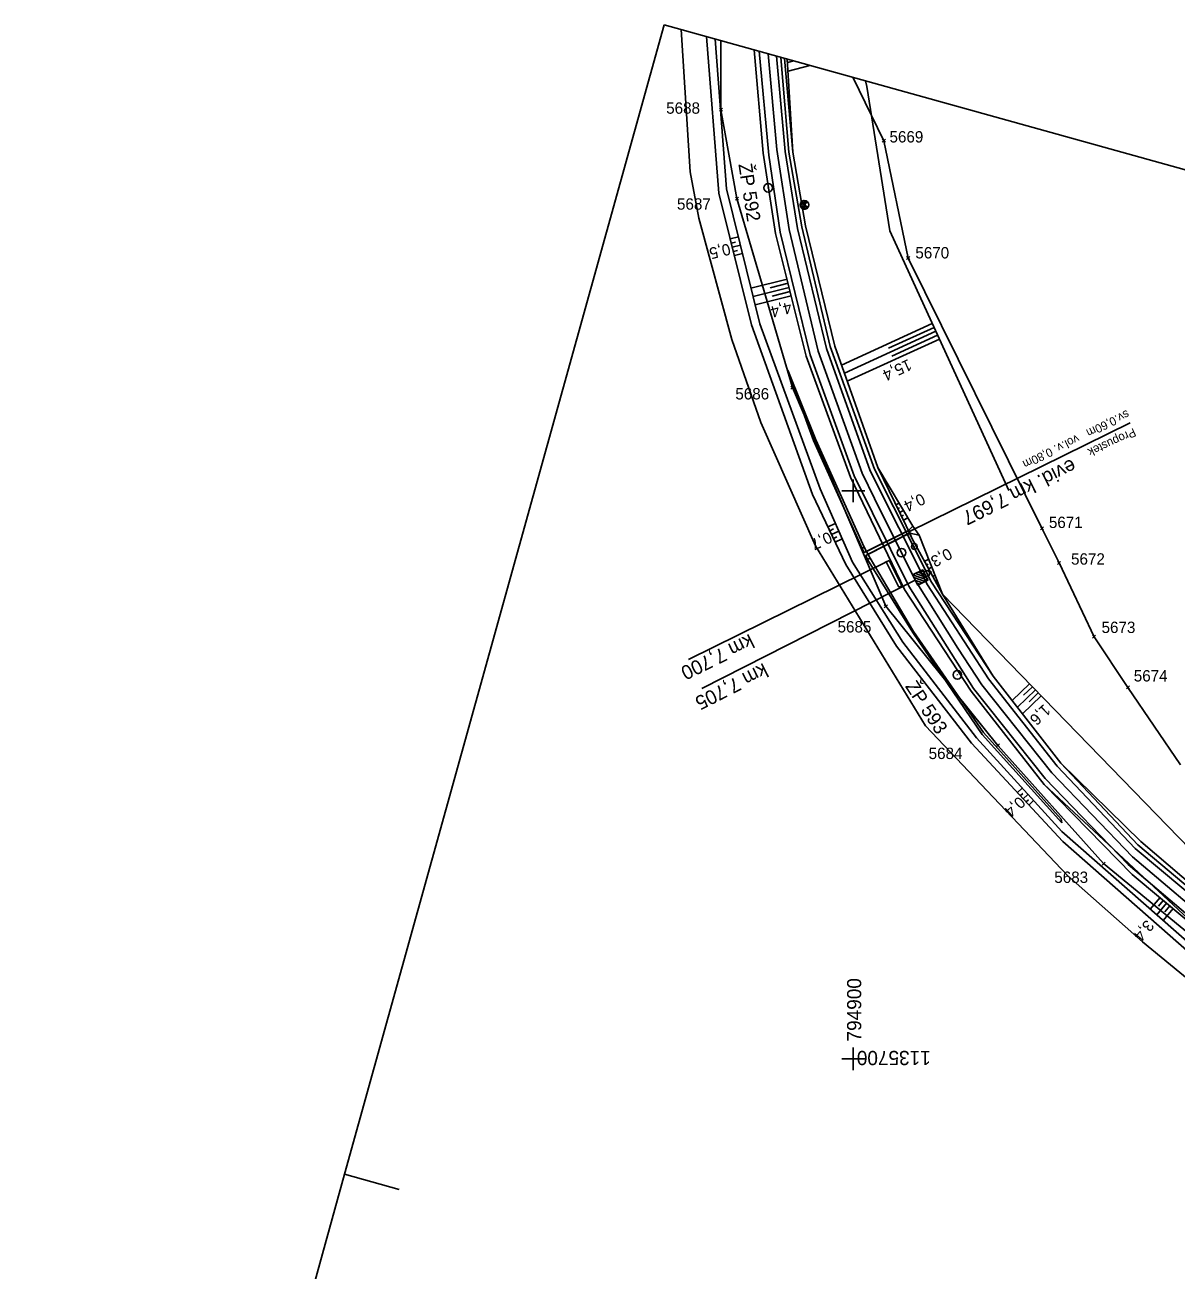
# Model space of a CAD drawing. Extents: x -795046 to -794647, y -1136002 to -1135518.
# Drawn here: x -795045.8 to -794843.2, y -1135737.2 to -1135518 of the extents above; entities that cross this region are included whole.
import ezdxf

# ---------------------------------------------------------------- set-up
doc = ezdxf.new("R2010")
doc.units = 0
for name, color, linetype in [('0381KM005-009P - Vrstva 1', 7, 'Continuous'), ('0381KM005-009P - Vrstva 13', 7, 'Continuous'), ('0381KM005-009P - Vrstva 19', 7, 'Continuous'), ('0381KM005-009P - Vrstva 28', 7, 'Continuous'), ('0381KM005-009P - Vrstva 3', 7, 'Continuous'), ('0381KM005-009P - Vrstva 4', 7, 'Continuous'), ('0381KM005-009P - Vrstva 48', 7, 'Continuous'), ('0381KM005-009P - Vrstva 49', 7, 'Continuous'), ('0381KM005-009P - Vrstva 51', 7, 'Continuous'), ('0381KM005-009P - Vrstva 55', 7, 'Continuous'), ('0381KM005-009P - Vrstva 7', 7, 'Continuous'), ('0381KM005-009P - Vrstva 9', 7, 'Continuous'), ('formát', 7, 'Continuous'), ('krizky_1000 - souradnice', 7, 'Continuous'), ('krizky_1000 - Vrstva 1', 7, 'Continuous'), ('szdc - hran DP', 7, 'Continuous'), ('szdc - szdc_cislo', 7, 'Continuous'), ('szdc - szdc_krizek', 7, 'Continuous'), ('vyt_sit - stávající', 7, 'Continuous')]:
    doc.layers.add(name, color=color, linetype=linetype)

msp = doc.modelspace()

# ---------------------------------------------------------------- linework, layer by layer
at = {"layer": '0381KM005-009P - Vrstva 1'}
msp.add_lwpolyline([(-794915, -1135523.08), (-794913.46, -1135539.92), (-794911.29, -1135554.01), (-794906.18, -1135575.42), (-794898.43, -1135596.89), (-794896.25, -1135601.39), (-794889.11, -1135615.73), (-794881.58, -1135627.73), (-794877.36, -1135634.16), (-794865.05, -1135649.67), (-794850.87, -1135664.43), (-794835.06, -1135677.82), (-794817.77, -1135689.58), (-794801.57, -1135698.91), (-794785.04, -1135707.72), (-794765.11, -1135718.4), (-794746.17, -1135729.82), (-794729.27, -1135742.41), (-794716.02, -1135754.58), (-794701.99, -1135770.6), (-794697.2, -1135777.62)], dxfattribs=at)
at = {"layer": '0381KM005-009P - Vrstva 13'}
for points in [[(-794898.09, -1135609.93), (-794898.09, -1135609.93), (-794906.6, -1135591.05), (-794911.52, -1135578.79), (-794907, -1135591.18), (-794898.46, -1135610.15), (-794898.09, -1135609.93)], [(-794897.05, -1135611.89), (-794897.51, -1135612.1), (-794889.51, -1135624.97), (-794877.31, -1135642.92), (-794863.33, -1135658.49)], [(-794863.33, -1135658.49), (-794863.44, -1135657.81), (-794877.06, -1135642.57), (-794889.39, -1135624.78), (-794897.05, -1135611.89)]]:
    msp.add_lwpolyline(points, dxfattribs=at)
at = {"layer": '0381KM005-009P - Vrstva 19'}
for p, q in [((-794890.22, -1135607.23), (-794851.25, -1135588.05)), ((-794898.08, -1135610.9), (-794890.26, -1135606.98)), ((-794890.03, -1135607.47), (-794897.8, -1135611.38)), ((-794890.24, -1135606.98), (-794897.66, -1135610.68)), ((-794897.41, -1135611.19), (-794890.06, -1135607.43))]:
    msp.add_line(p, q, dxfattribs=at)
for points in [[(-794890.7, -1135606.17), (-794890.26, -1135606.98), (-794890.24, -1135606.98), (-794890.06, -1135607.43), (-794890.03, -1135607.47), (-794889.7, -1135608.37)], [(-794898.09, -1135609.93), (-794897.05, -1135611.89), (-794897.51, -1135612.1), (-794897.8, -1135611.38), (-794897.41, -1135611.19), (-794897.66, -1135610.68), (-794898.08, -1135610.9), (-794898.46, -1135610.15)]]:
    msp.add_lwpolyline(points, close=True, dxfattribs=at)
at = {"layer": '0381KM005-009P - Vrstva 28'}
msp.add_line((-794887.06, -1135614.6), (-794887.11, -1135614.51), dxfattribs=at)
msp.add_circle((-794887.08, -1135614.55), 0.5, dxfattribs=at)
at = {"layer": '0381KM005-009P - Vrstva 3'}
for p, q in [((-794889.11, -1135615.73), (-794926.66, -1135634.8)), ((-794886.88, -1135615.74), (-794889.56, -1135614.84)), ((-794887.35, -1135615.97), (-794889.32, -1135615.31)), ((-794887.11, -1135615.26), (-794889.08, -1135614.6)), ((-794887.83, -1135616.21), (-794889.08, -1135615.79)), ((-794888.3, -1135616.45), (-794888.85, -1135616.26)), ((-794887.35, -1135614.79), (-794888.61, -1135614.36)), ((-794887.58, -1135614.31), (-794888.13, -1135614.13))]:
    msp.add_line(p, q, dxfattribs=at)
msp.add_lwpolyline([(-794888.67, -1135616.63), (-794889.56, -1135614.84), (-794887.76, -1135613.95), (-794886.88, -1135615.74)], close=True, dxfattribs=at)
at = {"layer": '0381KM005-009P - Vrstva 4'}
for points in [[(-794917.47, -1135522.4), (-794915.85, -1135540.59), (-794913.67, -1135554.7), (-794908.27, -1135576.33), (-794900.49, -1135597.63), (-794890.98, -1135617.37), (-794879.27, -1135635.32), (-794866.44, -1135651.71), (-794836.69, -1135679.46), (-794818.84, -1135691.63), (-794786.57, -1135709.39), (-794766.3, -1135721.02), (-794748.58, -1135730.93), (-794731.42, -1135743.47), (-794717.51, -1135756.55), (-794703.68, -1135772.07), (-794698, -1135780.52)], [(-794697.72, -1135779.5), (-794703.02, -1135771.54), (-794717.11, -1135755.66), (-794731.12, -1135742.73), (-794748.15, -1135730.35), (-794763.88, -1135720.89), (-794786.11, -1135708.79), (-794818.08, -1135691.13), (-794836.08, -1135678.99), (-794851.61, -1135665.79), (-794866.22, -1135650.67), (-794878.82, -1135634.83), (-794890.24, -1135616.8), (-794899.85, -1135597.37), (-794907.59, -1135576.09), (-794912.87, -1135554.46), (-794914.85, -1135540.94), (-794916.58, -1135522.65)], [(-794696.7, -1135775.84), (-794700.88, -1135769.71), (-794714.51, -1135754.08), (-794728.76, -1135740.91), (-794743.23, -1135730.04), (-794762.73, -1135718.04), (-794783.1, -1135707.11), (-794816.84, -1135688.49), (-794833.24, -1135677.32), (-794850.38, -1135662.96), (-794864.1, -1135648.49), (-794876.22, -1135633.13), (-794886.94, -1135616.58), (-794897.05, -1135596.51), (-794904.69, -1135574.95), (-794909.82, -1135553.82), (-794912.02, -1135540.3), (-794913.51, -1135523.5)], [(-794912.74, -1135523.71), (-794911.32, -1135540.41), (-794909.07, -1135553.52), (-794904.05, -1135574.62), (-794896.27, -1135596.21), (-794886.26, -1135616.08), (-794875.38, -1135632.64), (-794863.5, -1135647.94), (-794849.93, -1135662.35), (-794832.65, -1135676.88), (-794816.85, -1135687.92), (-794782.78, -1135706.49), (-794762.23, -1135717.77), (-794742.47, -1135729.7), (-794727.73, -1135739.54), (-794713.83, -1135753.13), (-794700.2, -1135769.22), (-794696.4, -1135774.74)]]:
    msp.add_lwpolyline(points, dxfattribs=at)
at = {"layer": '0381KM005-009P - Vrstva 48'}
for p, q in [((-794910.48, -1135524.34), (-794911.58, -1135524.64)), ((-794907.65, -1135525.13), (-794911.49, -1135526.17)), ((-794921.65, -1135555.69), (-794920.21, -1135555.33)), ((-794921.47, -1135556.42), (-794920.75, -1135556.24)), ((-794921.29, -1135557.15), (-794919.85, -1135556.79)), ((-794921.11, -1135557.88), (-794920.39, -1135557.7)), ((-794920.93, -1135558.6), (-794919.5, -1135558.25)), ((-794911.66, -1135562.77), (-794918.01, -1135564.35)), ((-794911.47, -1135563.49), (-794914.65, -1135564.29)), ((-794911.29, -1135564.22), (-794917.65, -1135565.81)), ((-794910.93, -1135565.68), (-794917.29, -1135567.27)), ((-794911.11, -1135564.95), (-794914.29, -1135565.74)), ((-794886.1, -1135570.57), (-794902.06, -1135577.88)), ((-794885.48, -1135571.93), (-794901.56, -1135579.3)), ((-794885.79, -1135571.25), (-794893.8, -1135574.92)), ((-794884.85, -1135573.3), (-794901.06, -1135580.72)), ((-794885.17, -1135572.61), (-794893.24, -1135576.31)), ((-794892.51, -1135602.47), (-794891.95, -1135602.19)), ((-794892.18, -1135603.14), (-794891.87, -1135602.99)), ((-794891.85, -1135603.81), (-794891.18, -1135603.49)), ((-794891.52, -1135604.49), (-794891.16, -1135604.31)), ((-794891.19, -1135605.16), (-794890.41, -1135604.78)), ((-794904.48, -1135606.38), (-794903.16, -1135605.75)), ((-794904.16, -1135607.05), (-794903.51, -1135606.74)), ((-794903.83, -1135607.73), (-794902.56, -1135607.12)), ((-794903.51, -1135608.41), (-794902.89, -1135608.11)), ((-794903.19, -1135609.08), (-794901.96, -1135608.5)), ((-794887.47, -1135612.45), (-794886.76, -1135612.05)), ((-794887.11, -1135613.1), (-794886.8, -1135612.93)), ((-794886.75, -1135613.76), (-794886.2, -1135613.46)), ((-794886.39, -1135614.42), (-794886.16, -1135614.29)), ((-794886.03, -1135615.08), (-794885.64, -1135614.87)), ((-794869.01, -1135633.98), (-794872.05, -1135636.93)), ((-794867.96, -1135635.05), (-794871.12, -1135638.12)), ((-794868.48, -1135634.52), (-794870.03, -1135636.02)), ((-794867.44, -1135635.59), (-794869.05, -1135637.16)), ((-794866.92, -1135636.13), (-794870.2, -1135639.31)), ((-794871.13, -1135653.14), (-794870.27, -1135652.34)), ((-794870.62, -1135653.69), (-794870.19, -1135653.29)), ((-794870.11, -1135654.24), (-794869.27, -1135653.46)), ((-794869.6, -1135654.79), (-794869.18, -1135654.4)), ((-794869.09, -1135655.34), (-794868.26, -1135654.56)), ((-794846.02, -1135671.64), (-794847.73, -1135673.69)), ((-794844.87, -1135672.6), (-794846.61, -1135674.68)), ((-794845.45, -1135672.12), (-794846.31, -1135673.15)), ((-794844.3, -1135673.09), (-794845.17, -1135674.13)), ((-794843.72, -1135673.57), (-794845.48, -1135675.67))]:
    msp.add_line(p, q, dxfattribs=at)
at = {"layer": '0381KM005-009P - Vrstva 49'}
for p, q in [((-794912.11, -1135523.89), (-794910.64, -1135540.4)), ((-794890.7, -1135606.17), (-794890.26, -1135606.98)), ((-794890.26, -1135606.98), (-794889.55, -1135606.22)), ((-794890.03, -1135607.47), (-794888.43, -1135607.82)), ((-794889.7, -1135608.37), (-794890.03, -1135607.47))]:
    msp.add_line(p, q, dxfattribs=at)
for points in [[(-794925.83, -1135520.07), (-794923.66, -1135547.6), (-794917.9, -1135570.81), (-794907.19, -1135600.69), (-794901.33, -1135612.99), (-794892.4, -1135627.36), (-794879.19, -1135644.46), (-794863.1, -1135661.78), (-794838.91, -1135683.03), (-794815.97, -1135701.12), (-794794.79, -1135715.61), (-794782.46, -1135721.1), (-794767.75, -1135725.5), (-794750.75, -1135732.17), (-794732.98, -1135744.75), (-794719.14, -1135757.73), (-794705.45, -1135773.64), (-794699.07, -1135784.37)], [(-794749.75, -1135730.99), (-794767.46, -1135724.56), (-794782.23, -1135720.17), (-794794.11, -1135714.55), (-794814.96, -1135700.02), (-794837.43, -1135682.73), (-794863.32, -1135660), (-794878.31, -1135643.5), (-794891.31, -1135626.67), (-794900.17, -1135612.61), (-794905.81, -1135599.68), (-794916.46, -1135570.65), (-794922.29, -1135546.83), (-794924.31, -1135520.49)], [(-794917.47, -1135522.4), (-794915.85, -1135540.59), (-794913.67, -1135554.7), (-794908.27, -1135576.33), (-794900.49, -1135597.63), (-794890.98, -1135617.37), (-794879.27, -1135635.32), (-794866.44, -1135651.71), (-794850.9, -1135667.56)], [(-794911.62, -1135524.02), (-794910.64, -1135540.4), (-794908.42, -1135553.38), (-794903.23, -1135574.56), (-794895.71, -1135595.89), (-794889.55, -1135606.22), (-794888.43, -1135607.82), (-794884.32, -1135618.22)], [(-794897.87, -1135527.85), (-794897.6, -1135528.83), (-794893.57, -1135554.26), (-794872.65, -1135599.94)], [(-794895.71, -1135595.89), (-794890.7, -1135606.17)], [(-794889.7, -1135608.37), (-794884.32, -1135618.22), (-794824.85, -1135679.44), (-794811.36, -1135687.77), (-794786.09, -1135699.38), (-794707.09, -1135741.45)], [(-794863.5, -1135647.94), (-794875.38, -1135632.64), (-794884.32, -1135618.22)], [(-794695.93, -1135773.08), (-794698.78, -1135768.51), (-794712.94, -1135751.52), (-794727.73, -1135739.54), (-794743.72, -1135728.23), (-794763.92, -1135716.02), (-794781.48, -1135706.54), (-794800.89, -1135696.32), (-794816.57, -1135687.28), (-794832.17, -1135676.47), (-794849.4, -1135661.77), (-794863.5, -1135647.94)], [(-794850.9, -1135667.56), (-794836.69, -1135679.46), (-794818.84, -1135691.63), (-794803.16, -1135702.98), (-794784.32, -1135712.45), (-794768.51, -1135721.35), (-794758.17, -1135725.72), (-794749.71, -1135730.94)]]:
    msp.add_lwpolyline(points, dxfattribs=at)
at = {"layer": '0381KM005-009P - Vrstva 51'}
msp.add_lwpolyline([(-794699.07, -1135784.37), (-794705.45, -1135773.64), (-794719.14, -1135757.73), (-794732.98, -1135744.75), (-794750.75, -1135732.17), (-794767.75, -1135725.5), (-794782.46, -1135721.1), (-794794.79, -1135715.61), (-794815.97, -1135701.12), (-794838.91, -1135683.03), (-794863.1, -1135661.78), (-794879.19, -1135644.46), (-794892.4, -1135627.36), (-794901.33, -1135612.99), (-794907.19, -1135600.69), (-794917.9, -1135570.81), (-794923.66, -1135547.6), (-794925.83, -1135520.07)], dxfattribs=at)
at = {"layer": '0381KM005-009P - Vrstva 55'}
msp.add_lwpolyline([(-794930.32, -1135518.82), (-794928.69, -1135543.86), (-794927.18, -1135552.03), (-794921.37, -1135573.41), (-794916.26, -1135587.98), (-794906.67, -1135609.69), (-794887.27, -1135641.42), (-794862.33, -1135667.74), (-794849.1, -1135679.42), (-794837.63, -1135688.88), (-794826.42, -1135697.51), (-794808.25, -1135711.35), (-794792.02, -1135721.49), (-794781.13, -1135725.75), (-794765.57, -1135730.81), (-794749.96, -1135737.95), (-794742.14, -1135743.85), (-794737.72, -1135738.96), (-794727.83, -1135728.01), (-794718.43, -1135717.37), (-794692.54, -1135688.86), (-794715.68, -1135650.06)], dxfattribs=at)
at = {"layer": '0381KM005-009P - Vrstva 7'}
msp.add_line((-794889.24, -1135609.86), (-794889.28, -1135609.77), dxfattribs=at)
for centre, radius in [((-794889.26, -1135609.81), 0.5), ((-794891.51, -1135610.91), 0.75)]:
    msp.add_circle(centre, radius, dxfattribs=at)
at = {"layer": '0381KM005-009P - Vrstva 9'}
for p, q in [((-794893.93, -1135612.39), (-794929, -1135629.69)), ((-794894.19, -1135612.52), (-794894.73, -1135612.79)), ((-794893.66, -1135612.26), (-794894.19, -1135612.52)), ((-794894.19, -1135612.52), (-794892, -1135617.01)), ((-794891.46, -1135616.75), (-794893.66, -1135612.26)), ((-794892, -1135617.01), (-794891.46, -1135616.75))]:
    msp.add_line(p, q, dxfattribs=at)
at = {"layer": 'formát'}
for p, q in [((-794933.28, -1135518), (-794989.53, -1135720.33)), ((-794933.28, -1135518), (-794647.13, -1135597.56)), ((-794989.53, -1135720.33), (-795045.79, -1135922.65)), ((-794989.53, -1135720.33), (-794979.9, -1135723.01))]:
    msp.add_line(p, q, dxfattribs=at)
at = {"layer": 'krizky_1000 - Vrstva 1'}
for points in [[(-794900, -1135598), (-794900, -1135602)], [(-794902, -1135600), (-794898, -1135600)], [(-794900, -1135698), (-794900, -1135702)], [(-794902, -1135700), (-794898, -1135700)]]:
    msp.add_lwpolyline(points, dxfattribs=at)
at = {"layer": 'szdc - hran DP'}
for p, q in [((-794923.29, -1135532.94), (-794923.3, -1135520.77)), ((-794900.1, -1135527.22), (-794894.63, -1135538.4)), ((-794920.48, -1135548.58), (-794923.29, -1135532.94)), ((-794894.63, -1135538.4), (-794890.34, -1135559.06)), ((-794910.72, -1135581.84), (-794920.48, -1135548.58)), ((-794890.34, -1135559.06), (-794866.81, -1135606.62)), ((-794894.27, -1135620.34), (-794910.72, -1135581.84)), ((-794866.81, -1135606.62), (-794863.8, -1135612.72)), ((-794863.8, -1135612.72), (-794857.64, -1135625.71)), ((-794874.54, -1135644.85), (-794894.27, -1135620.34)), ((-794857.64, -1135625.71), (-794851.67, -1135634.62)), ((-794851.67, -1135634.62), (-794842.4, -1135648.25)), ((-794855.96, -1135665.64), (-794874.54, -1135644.85)), ((-794807.25, -1135705.8), (-794855.96, -1135665.64))]:
    msp.add_line(p, q, dxfattribs=at)
at = {"layer": 'szdc - szdc_krizek'}
for p, q in [((-794923.03, -1135533.21), (-794923.56, -1135532.68)), ((-794923.56, -1135533.21), (-794923.03, -1135532.68)), ((-794894.36, -1135538.67), (-794894.9, -1135538.14)), ((-794894.9, -1135538.67), (-794894.36, -1135538.14)), ((-794920.21, -1135548.84), (-794920.75, -1135548.31)), ((-794920.75, -1135548.84), (-794920.21, -1135548.31)), ((-794890.08, -1135559.32), (-794890.61, -1135558.79)), ((-794890.61, -1135559.32), (-794890.08, -1135558.79)), ((-794910.46, -1135582.1), (-794910.99, -1135581.57)), ((-794910.99, -1135582.1), (-794910.46, -1135581.57)), ((-794866.55, -1135606.89), (-794867.08, -1135606.35)), ((-794867.08, -1135606.89), (-794866.55, -1135606.35)), ((-794863.54, -1135612.99), (-794864.07, -1135612.46)), ((-794864.07, -1135612.99), (-794863.54, -1135612.46)), ((-794894.01, -1135620.6), (-794894.54, -1135620.07)), ((-794894.54, -1135620.6), (-794894.01, -1135620.07)), ((-794857.38, -1135625.98), (-794857.91, -1135625.45)), ((-794857.91, -1135625.98), (-794857.38, -1135625.45)), ((-794851.41, -1135634.89), (-794851.94, -1135634.35)), ((-794851.94, -1135634.89), (-794851.41, -1135634.35)), ((-794874.28, -1135645.11), (-794874.81, -1135644.58)), ((-794874.81, -1135645.11), (-794874.28, -1135644.58)), ((-794855.7, -1135665.91), (-794856.23, -1135665.38)), ((-794856.23, -1135665.91), (-794855.7, -1135665.38))]:
    msp.add_line(p, q, dxfattribs=at)
at = {"layer": 'vyt_sit - stávající'}
for p, q in [((-794914.98, -1135546.62), (-794914.96, -1135546.72)), ((-794908.58, -1135549.69), (-794909.2, -1135549.24)), ((-794908.46, -1135549.52), (-794909.05, -1135549.09)), ((-794909.02, -1135550.3), (-794908.58, -1135549.69)), ((-794908.4, -1135550.43), (-794908.87, -1135550.09)), ((-794908.28, -1135549.28), (-794908.74, -1135548.94)), ((-794908.1, -1135550.28), (-794908.69, -1135549.85)), ((-794908.13, -1135549.07), (-794908.58, -1135549.69)), ((-794908.58, -1135549.69), (-794907.96, -1135550.14)), ((-794881.72, -1135632.38), (-794881.67, -1135632.47))]:
    msp.add_line(p, q, dxfattribs=at)
for centre, radius in [((-794914.97, -1135546.67), 0.756), ((-794908.58, -1135549.69), 0.764), ((-794881.69, -1135632.43), 0.756)]:
    msp.add_circle(centre, radius, dxfattribs=at)
for radius, start, end in [(0.765, 53.9818, 143.8753), (0.764, 233.293, 323.611)]:
    msp.add_arc((-794908.58, -1135549.69), radius, start, end, dxfattribs=at)

# ---------------------------------------------------------------- texts
at = {"layer": '0381KM005-009P - Vrstva 19'}
for s, height, rotation, p in [('sv.0,60m   vol.v. 0,80m', 1.5, 206.2068, (-794851.86, -1135585.74)), ('Propustek', 1.5, 204.6627, (-794850.69, -1135588.94)), ('evid. km 7,697', 2.5, 206.2068, (-794861.56, -1135594.31))]:
    msp.add_text(s, height=height, rotation=rotation, dxfattribs=at).set_placement(p)
at = {"layer": '0381KM005-009P - Vrstva 3'}
msp.add_text('km 7,705', height=2.5, rotation=206.9201, dxfattribs=at).set_placement((-794915.82, -1135630.27))
at = {"layer": '0381KM005-009P - Vrstva 48'}
for s, rotation, p in [('0,5', 193.9485, (-794921.9, -1135556.44)), ('4,4', 194.0238, (-794911.11, -1135566.74)), ('15,4', 204.6063, (-794890.3, -1135576.77)), ('0,4', 205.994, (-794887.97, -1135600.39)), ('0,7', 205.5118, (-794904.35, -1135607.14)), ('0,3', 208.6712, (-794883.32, -1135610.02)), ('1,6', 224.1646, (-794866.45, -1135637.45)), ('0,4', 222.9053, (-794870.87, -1135653.69)), ('3,4', 230.0673, (-794848.42, -1135675.4))]:
    msp.add_text(s, height=2, rotation=rotation, dxfattribs=at).set_placement(p)
at = {"layer": '0381KM005-009P - Vrstva 9'}
msp.add_text('km 7,700', height=2.5, rotation=206.0861, dxfattribs=at).set_placement((-794918.25, -1135625.14))
at = {"layer": 'krizky_1000 - souradnice'}
for s, rotation, p in [('794900', 90, (-794898.6, -1135696.96)), ('1135700', 180, (-794886.37, -1135698.62))]:
    msp.add_text(s, height=2.5, rotation=rotation, dxfattribs=at).set_placement(p)
at = {"layer": 'szdc - szdc_cislo'}
for s, p in [('5688', (-794932.93, -1135533.64)), ('5669', (-794893.63, -1135538.7)), ('5687', (-794931.03, -1135550.53)), ('5670', (-794889.08, -1135559.11)), ('5686', (-794920.76, -1135583.94)), ('5671', (-794865.58, -1135606.57)), ('5672', (-794861.68, -1135613.02)), ('5685', (-794902.77, -1135624.96)), ('5673', (-794856.31, -1135625.05)), ('5674', (-794850.64, -1135633.59)), ('5684', (-794886.74, -1135647.24)), ('5683', (-794864.63, -1135669.05))]:
    msp.add_text(s, height=2, dxfattribs=at).set_placement(p)
at = {"layer": 'vyt_sit - stávající'}
for s, rotation, p in [('ŽP 592', 278.77, (-794920.23, -1135542.54)), ('ŽP 593', 303.3346, (-794890.95, -1135634.44))]:
    msp.add_text(s, height=2.4, rotation=rotation, dxfattribs=at).set_placement(p)

doc.saveas('drawing.dxf')
